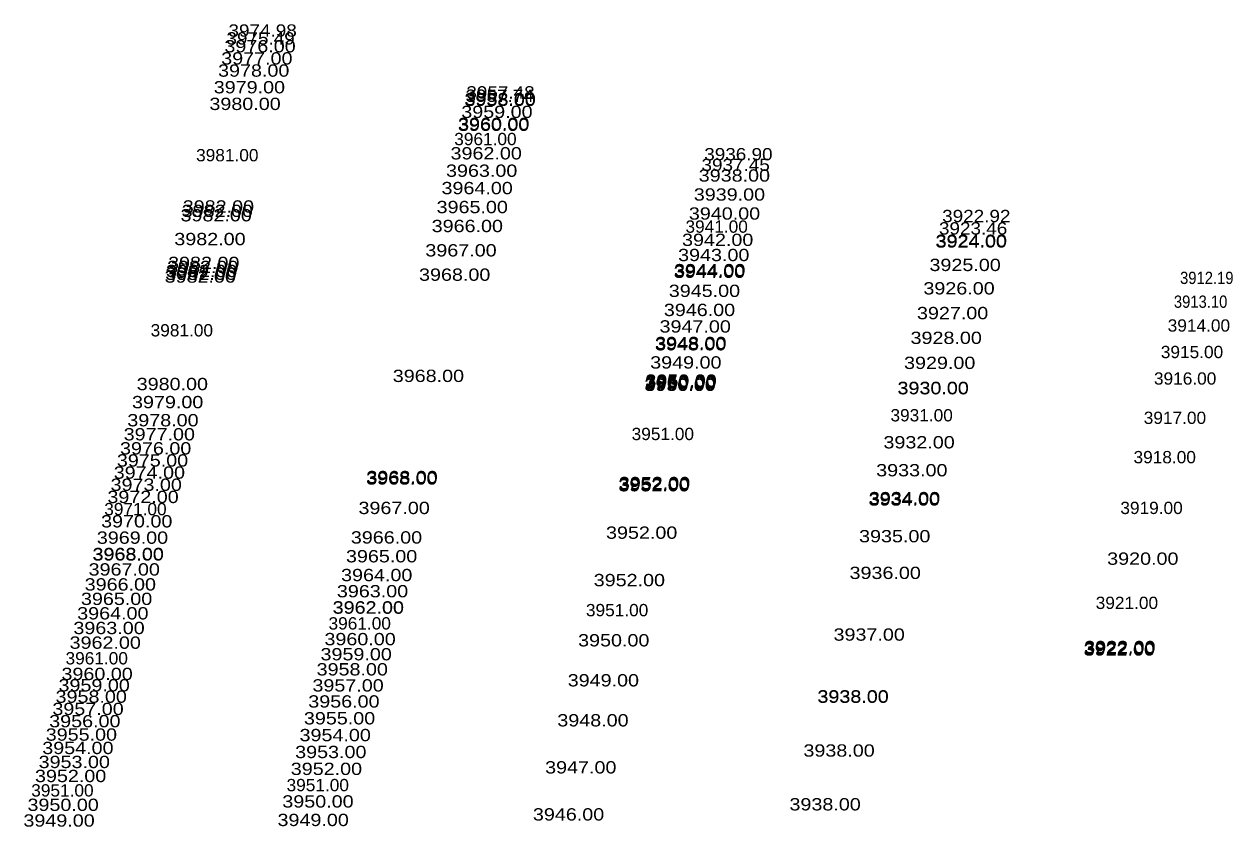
# Model space of a CAD drawing. Extents: x 49942 to 56479, y 47140 to 53283.
# Drawn here: x 55301 to 55792.7, y 49695 to 50021.3 of the extents above; entities that cross this region are included whole.
import ezdxf

# ---------------------------------------------------------------- set-up
doc = ezdxf.new("R2010")
doc.units = 0
doc.header["$LTSCALE"] = 2
doc.layers.add('29', color=7, linetype='Continuous')

msp = doc.modelspace()

# ---------------------------------------------------------------- texts
at = {"layer": '29'}
for s, width, p in [('3974.98', 1.15, (55384.062, 50016.235)), ('3976.00', 1.2, (55382.405, 50009.858)), ('3975.49', 1.15, (55383.233, 50013.046)), ('3977.00', 1.2, (55381.12, 50004.91)), ('3978.00', 1.2, (55379.835, 49999.962)), ('3979.00', 1.2, (55378.075, 49993.187)), ('3957.74', 1.15, (55480.493, 49989.721)), ('3957.48', 1.15, (55480.85, 49991.096)), ('3980.00', 1.2, (55376.316, 49986.412)), ('3958.00', 1.2, (55480.058, 49988.045)), ('3958.00', 1.2, (55480.097, 49988.195)), ('3958.00', 1.2, (55480.136, 49988.345)), ('3959.00', 1.2, (55478.79, 49983.162)), ('3960.00', 1.2, (55477.427, 49977.914)), ('3960.00', 1.2, (55477.472, 49978.091)), ('3960.00', 1.2, (55477.518, 49978.267)), ('3961.00', 1.05, (55475.921, 49972.119)), ('3981.00', 1.05, (55370.899, 49965.557)), ('3962.00', 1.2, (55474.416, 49966.323)), ('3936.90', 1.15, (55577.639, 49965.957)), ('3937.45', 1.15, (55576.516, 49961.633)), ('3963.00', 1.2, (55472.58, 49959.253)), ('3938.00', 1.2, (55575.393, 49957.308)), ('3964.00', 1.2, (55470.743, 49952.183)), ('3939.00', 1.2, (55573.384, 49949.575)), ('3982.00', 1.2, (55364.559, 49941.145)), ('3982.00', 1.2, (55365.021, 49942.924)), ('3982.00', 1.2, (55365.483, 49944.703)), ('3965.00', 1.2, (55468.742, 49944.477)), ('3940.00', 1.2, (55571.376, 49941.842)), ('3922.92', 1.15, (55674.427, 49940.819)), ('3966.00', 1.2, (55466.74, 49936.771)), ('3941.00', 1.05, (55569.995, 49936.526)), ('3923.46', 1.15, (55673.122, 49935.79)), ('3982.00', 1.2, (55362.043, 49931.459)), ('3942.00', 1.2, (55568.597, 49931.143)), ('3924.00', 1.2, (55671.739, 49930.466)), ('3924.00', 1.2, (55671.778, 49930.618)), ('3924.00', 1.2, (55671.816, 49930.762)), ('3967.00', 1.2, (55464.17, 49926.875)), ('3982.00', 1.2, (55359.527, 49921.773)), ('3943.00', 1.2, (55566.996, 49924.98)), ('3925.00', 1.2, (55669.267, 49920.948)), ('3982.00', 1.2, (55358.085, 49916.222)), ('3982.00', 1.2, (55358.376, 49917.343)), ('3982.00', 1.2, (55358.668, 49918.464)), ('3982.00', 1.2, (55359.097, 49920.119)), ('3968.00', 1.2, (55461.6, 49916.98)), ('3944.00', 1.2, (55565.226, 49918.166)), ('3944.00', 1.2, (55565.311, 49918.492)), ('3944.00', 1.2, (55565.395, 49918.818)), ('3912.19', 0.9, (55771.216, 49915.68)), ('3926.00', 1.2, (55666.795, 49911.43)), ('3945.00', 1.2, (55563.211, 49910.409)), ('3913.10', 0.9, (55768.702, 49905.998)), ('3946.00', 1.2, (55561.197, 49902.652)), ('3927.00', 1.2, (55664.18, 49901.365)), ('3947.00', 1.2, (55559.449, 49895.925)), ('3914.00', 1.05, (55766.187, 49896.316)), ('3981.00', 1.05, (55352.41, 49894.371)), ('3928.00', 1.2, (55661.566, 49891.3)), ('3948.00', 1.2, (55557.57, 49888.687)), ('3948.00', 1.2, (55557.636, 49888.942)), ('3948.00', 1.2, (55557.702, 49889.198)), ('3949.00', 1.2, (55555.651, 49881.299)), ('3929.00', 1.2, (55658.924, 49881.128)), ('3915.00', 1.05, (55763.388, 49885.54)), ('3980.00', 1.2, (55346.734, 49872.519)), ('3968.00', 1.2, (55450.914, 49875.836)), ('3950.00', 1.2, (55553.284, 49872.189)), ('3950.00', 1.2, (55553.425, 49872.729)), ('3950.00', 1.2, (55553.565, 49873.268)), ('3950.00', 1.2, (55553.648, 49873.59)), ('3950.00', 1.2, (55553.732, 49873.911)), ('3916.00', 1.05, (55760.589, 49874.764)), ('3930.00', 1.2, (55656.245, 49870.814)), ('3930.00', 1.2, (55656.262, 49870.879)), ('3930.00', 1.2, (55656.279, 49870.944)), ('3979.00', 1.2, (55344.826, 49865.17)), ('3978.00', 1.2, (55342.913, 49857.806)), ('3931.00', 1.05, (55653.392, 49859.828)), ('3917.00', 1.05, (55756.438, 49858.779)), ('3977.00', 1.2, (55341.428, 49852.09)), ('3951.00', 1.05, (55548.099, 49852.223)), ('3932.00', 1.2, (55650.538, 49848.841)), ('3976.00', 1.2, (55339.944, 49846.375)), ('3918.00', 1.05, (55752.286, 49842.795)), ('3975.00', 1.2, (55338.664, 49841.447)), ('3933.00', 1.2, (55647.589, 49837.484)), ('3974.00', 1.2, (55337.384, 49836.52)), ('3968.00', 1.2, (55440.084, 49834.138)), ('3968.00', 1.2, (55440.098, 49834.195)), ('3968.00', 1.2, (55440.113, 49834.252)), ('3968.00', 1.2, (55440.17, 49834.472)), ('3968.00', 1.2, (55440.227, 49834.692)), ('3952.00', 1.2, (55542.913, 49832.257)), ('3973.00', 1.2, (55336.099, 49831.572)), ('3952.00', 1.2, (55542.684, 49831.377)), ('3952.00', 1.2, (55542.799, 49831.817)), ('3972.00', 1.2, (55334.814, 49826.625)), ('3967.00', 1.2, (55436.969, 49822.145)), ('3934.00', 1.2, (55644.495, 49825.575)), ('3934.00', 1.2, (55644.567, 49825.851)), ('3934.00', 1.2, (55644.639, 49826.127)), ('3919.00', 1.05, (55746.927, 49822.161)), ('3971.00', 1.05, (55333.527, 49821.669)), ('3970.00', 1.2, (55332.24, 49816.714)), ('3969.00', 1.2, (55330.513, 49810.065)), ('3966.00', 1.2, (55433.854, 49810.152)), ('3952.00', 1.2, (55537.675, 49812.092)), ('3935.00', 1.2, (55640.622, 49810.662)), ('3968.00', 1.2, (55328.741, 49803.242)), ('3968.00', 1.2, (55328.765, 49803.335)), ('3968.00', 1.2, (55328.786, 49803.416)), ('3965.00', 1.2, (55431.868, 49802.508)), ('3920.00', 1.2, (55741.567, 49801.528)), ('3967.00', 1.2, (55327.158, 49797.147)), ('3964.00', 1.2, (55429.883, 49794.863)), ('3952.00', 1.2, (55532.666, 49792.805)), ('3936.00', 1.2, (55636.749, 49795.749)), ('3966.00', 1.2, (55325.575, 49791.053)), ('3963.00', 1.2, (55428.177, 49788.297)), ('3965.00', 1.2, (55324.05, 49785.179)), ('3921.00', 1.05, (55736.899, 49783.555)), ('3964.00', 1.2, (55322.524, 49779.305)), ('3962.00', 1.2, (55426.442, 49781.616)), ('3962.00', 1.2, (55426.455, 49781.667)), ('3962.00', 1.2, (55426.468, 49781.717)), ('3951.00', 1.05, (55529.497, 49780.603)), ('3963.00', 1.2, (55320.975, 49773.342)), ('3961.00', 1.05, (55424.779, 49775.212)), ('3960.00', 1.2, (55423.116, 49768.809)), ('3950.00', 1.2, (55526.312, 49768.34)), ('3937.00', 1.2, (55630.235, 49770.669)), ('3962.00', 1.2, (55319.426, 49767.379)), ('3922.00', 1.2, (55731.976, 49764.598)), ('3922.00', 1.2, (55732.104, 49765.09)), ('3922.00', 1.2, (55732.231, 49765.582)), ('3961.00', 1.05, (55317.777, 49761.028)), ('3959.00', 1.2, (55421.521, 49762.67)), ('3960.00', 1.2, (55316.125, 49754.667)), ('3958.00', 1.2, (55419.927, 49756.532)), ('3959.00', 1.2, (55314.927, 49750.054)), ('3957.00', 1.2, (55418.231, 49750.001)), ('3949.00', 1.2, (55522.087, 49752.075)), ('3958.00', 1.2, (55313.725, 49745.428)), ('3956.00', 1.2, (55416.535, 49743.471)), ('3938.00', 1.2, (55623.67, 49745.395)), ('3938.00', 1.2, (55623.69, 49745.473)), ('3938.00', 1.2, (55623.711, 49745.551)), ('3957.00', 1.2, (55312.429, 49740.44)), ('3956.00', 1.2, (55311.134, 49735.451)), ('3955.00', 1.2, (55414.759, 49736.635)), ('3948.00', 1.2, (55517.863, 49735.81)), ('3955.00', 1.2, (55309.721, 49730.011)), ('3954.00', 1.2, (55412.984, 49729.799)), ('3954.00', 1.2, (55308.308, 49724.571)), ('3953.00', 1.2, (55306.828, 49718.874)), ('3953.00', 1.2, (55411.2, 49722.933)), ('3938.00', 1.2, (55617.99, 49723.526)), ('3952.00', 1.2, (55409.417, 49716.067)), ('3947.00', 1.2, (55512.895, 49716.683)), ('3952.00', 1.2, (55305.348, 49713.176)), ('3951.00', 1.05, (55407.704, 49709.47)), ('3951.00', 1.05, (55303.825, 49707.312)), ('3950.00', 1.2, (55302.302, 49701.448)), ('3950.00', 1.2, (55405.977, 49702.822)), ('3938.00', 1.2, (55612.31, 49701.658)), ('3949.00', 1.2, (55300.646, 49695.073)), ('3949.00', 1.2, (55404.023, 49695.3)), ('3946.00', 1.2, (55507.927, 49697.556))]:
    msp.add_text(s, height=5, dxfattribs=dict(at, width=width)).set_placement(p)

doc.saveas('drawing.dxf')
